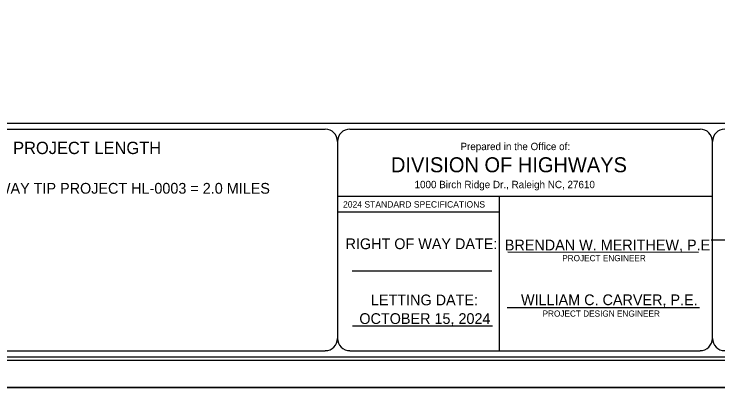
# Model space of a CAD drawing. Extents: x 925297 to 940193, y 663541 to 689899.
# Drawn here: x 930888 to 935468, y 681019 to 683528 of the extents above; entities that cross this region are included whole.
import ezdxf

# ---------------------------------------------------------------- set-up
doc = ezdxf.new("R2010")
doc.units = 0
for name, color, linetype in [('Sheet Cutting Line CELL', 7, 'Continuous'), ('Sheet Data Field CELL', 7, 'Continuous'), ('Sheet Plot Border Inside CELL', 7, 'Continuous'), ('Sheet Plot Border Outside CELL', 7, 'Continuous'), ('Sheet Title CELL', 7, 'Continuous')]:
    doc.layers.add(name, color=color, linetype=linetype)

msp = doc.modelspace()

# ---------------------------------------------------------------- linework, layer by layer
at = {"layer": 'Sheet Cutting Line CELL'}
msp.add_line((925296.7, 681098.7), (938768.7, 681098.7), dxfattribs=at)
at = {"layer": 'Sheet Plot Border Inside CELL'}
msp.add_lwpolyline([(925400.7, 681278.2), (938732.7, 681278.2), (938732.7, 689719), (925400.7, 689719)], close=True, dxfattribs=at)
at = {"layer": 'Sheet Plot Border Outside CELL'}
for points in [[(938768.7, 689898.6), (925296.7, 689898.6), (925296.7, 681098.7), (938768.7, 681098.7)], [(925296.7, 672338.7), (938764.7, 672338.7), (938764.7, 681098.7), (925296.7, 681098.7)]]:
    msp.add_lwpolyline(points, close=True, dxfattribs=at)
at = {"layer": 'Sheet Title CELL'}
for p, q in [((927152.7, 682818.7), (938512.7, 682818.7)), ((929872.7, 682778.6), (932912.7, 682778.6)), ((933072.7, 682778.7), (935352.7, 682778.7)), ((932992.7, 682698.7), (932992.7, 681418.7)), ((935432.7, 681418.6), (935432.7, 682698.6)), ((935432.7, 682340.6), (932992.7, 682340.7)), ((934045.1, 682340.7), (934045.1, 681338.7)), ((934045.1, 682238.6), (932992.7, 682238.7)), ((933741.9, 682238.7), (933741.9, 682238.7)), ((935425.5, 682058.9), (937190.9, 682058.9)), ((934100.3, 681980.7), (935341.5, 681980.6)), ((933997.1, 681855.9), (933087.1, 681855.9)), ((933541.9, 681855.8), (933541.9, 681855.8)), ((934097.5, 681620.7), (935347.5, 681620.7)), ((934000.3, 681499.1), (933090.3, 681499.1))]:
    msp.add_line(p, q, dxfattribs=at)
for points in [[(929872.7, 681338.6), (932912.7, 681338.6)], [(933072.7, 681338.7), (935352.7, 681338.6)], [(926712.7, 681298.6), (938552.7, 681298.6)]]:
    msp.add_lwpolyline(points, dxfattribs=at)
for centre, start, end in [((932912.7, 682699.1), 0, 90), ((933072.7, 682699.1), 90, 180), ((935352.7, 682699.1), 0, 90), ((935512.7, 682699.1), 90, 180), ((932912.7, 681419.1), 270, 360), ((933072.7, 681419.1), 180, 270), ((935352.7, 681419.1), 270, 360), ((935512.7, 681419.1), 180, 270)]:
    msp.add_arc(centre, 80, start, end, dxfattribs=at)

# ---------------------------------------------------------------- texts
at = {"layer": 'Sheet Data Field CELL'}
for s, p in [('LENGTH ROADWAY TIP PROJECT HL-0003 = 2.0 MILES', (930100, 682359.8)), ('BRENDAN W. MERITHEW, P.E.', (934081.7, 681991)), ('WILLIAM C. CARVER, P.E.', (934187, 681634.8)), ('OCTOBER 15, 2024', (933134.8, 681512.6))]:
    msp.add_text(s, height=70.001, dxfattribs=at).set_placement(p)
at = {"layer": 'Sheet Title CELL'}
for s, height, p in [('PROJECT LENGTH', 79.997, (930881.5, 682617.5)), ('Prepared in the Office of:', 47.995, (933792.7, 682643)), ('DIVISION OF HIGHWAYS', 97.498, (933340.6, 682499.1)), ('1000 Birch Ridge Dr., Raleigh NC, 27610', 48, (933494, 682395.5)), ('RIGHT OF WAY DATE: ', 69.998, (933045.1, 681999.1)), ('PROJECT ENGINEER', 39.996, (934455.1, 681920.7)), ('LETTING DATE:', 69.998, (933210.3, 681633.9)), ('PROJECT DESIGN ENGINEER', 39.996, (934327.1, 681560.2))]:
    msp.add_text(s, height=height, rotation=360, dxfattribs=at).set_placement(p)
msp.add_text('2024 STANDARD SPECIFICATIONS', height=41.6, dxfattribs=at).set_placement((933028.6, 682269.5))

doc.saveas('drawing.dxf')
